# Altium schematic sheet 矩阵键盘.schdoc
size 297 x 210 mm; Symbol: Sheet-Symbol_A4; Company: 嘉立创EDA; Version: V1.0; Page Size: A4; @Project Name: 矩阵键盘; @Page Count: 1; @Update Date: 2024-04-23; @Create Date: 2024-04-23; @Schematic Name: Schematic1; @Page No: 1; @Page Name: P1; Device: Sheet-Symbol_A4
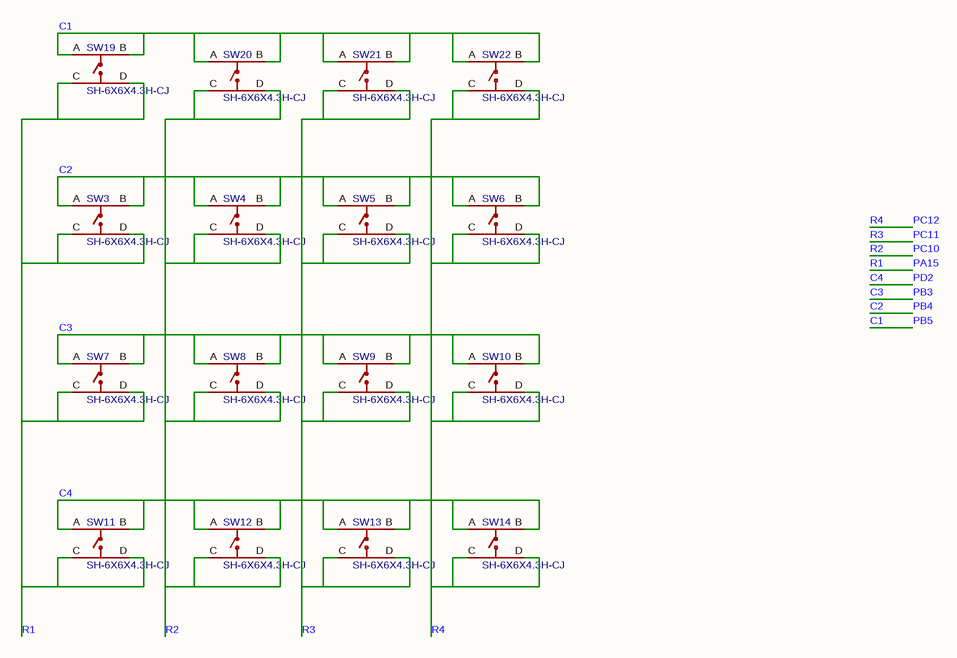
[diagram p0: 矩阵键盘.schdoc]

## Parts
SW3  SH-6X6X4.3H-CJ  [SW-TH_SH-6X6X4.3H-CJ]
SW4  SH-6X6X4.3H-CJ  [SW-TH_SH-6X6X4.3H-CJ]
SW5  SH-6X6X4.3H-CJ  [SW-TH_SH-6X6X4.3H-CJ]
SW6  SH-6X6X4.3H-CJ  [SW-TH_SH-6X6X4.3H-CJ]
SW7  SH-6X6X4.3H-CJ  [SW-TH_SH-6X6X4.3H-CJ]
SW8  SH-6X6X4.3H-CJ  [SW-TH_SH-6X6X4.3H-CJ]
SW9  SH-6X6X4.3H-CJ  [SW-TH_SH-6X6X4.3H-CJ]
SW10  SH-6X6X4.3H-CJ  [SW-TH_SH-6X6X4.3H-CJ]
SW11  SH-6X6X4.3H-CJ  [SW-TH_SH-6X6X4.3H-CJ]
SW12  SH-6X6X4.3H-CJ  [SW-TH_SH-6X6X4.3H-CJ]
SW13  SH-6X6X4.3H-CJ  [SW-TH_SH-6X6X4.3H-CJ]
SW14  SH-6X6X4.3H-CJ  [SW-TH_SH-6X6X4.3H-CJ]
SW19  SH-6X6X4.3H-CJ  [SW-TH_SH-6X6X4.3H-CJ]
SW20  SH-6X6X4.3H-CJ  [SW-TH_SH-6X6X4.3H-CJ]
SW21  SH-6X6X4.3H-CJ  [SW-TH_SH-6X6X4.3H-CJ]
SW22  SH-6X6X4.3H-CJ  [SW-TH_SH-6X6X4.3H-CJ]

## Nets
C1: SW19.A SW19.B SW20.A SW20.B SW21.A SW21.B SW22.A SW22.B  [also labelled PB5]
C2: SW3.A SW3.B SW4.A SW4.B SW5.A SW5.B SW6.A SW6.B  [also labelled PB4]
C3: SW7.A SW7.B SW8.A SW8.B SW9.A SW9.B SW10.A SW10.B  [also labelled PB3]
C4: SW11.A SW11.B SW12.A SW12.B SW13.A SW13.B SW14.A SW14.B  [also labelled PD2]
PA15: SW3.C SW3.D SW7.C SW7.D SW11.C SW11.D SW19.C SW19.D  [also labelled R1]
PC10: SW4.C SW4.D SW8.C SW8.D SW12.C SW12.D SW20.C SW20.D  [also labelled R2]
PC11: SW5.C SW5.D SW9.C SW9.D SW13.C SW13.D SW21.C SW21.D  [also labelled R3]
PC12: SW6.C SW6.D SW10.C SW10.D SW14.C SW14.D SW22.C SW22.D  [also labelled R4]

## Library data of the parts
SW3-SW14 SW19-SW22 = SH-6X6X4.3H-CJ: 电路结构:单刀单掷;按钮形状:圆形按钮;作用力:2.5N;安装方式:直插;开关长度:6mm;开关宽度:6mm;开关高度:4.3mm;带支架:不带支架;触点电流:50mA;额定电压:12V;带灯:无;工作寿命:10万次;; Manufacturer: SHOU HAN(首韩); 3D Model: 7465a1c6ddb3456bb37faad11a123e5a0819f05c4eef4c71ace90d822a990e87; 3D Model Transform: 236.22,307.086,0,90,0,0,0,0,-137.795; Circuit: 单刀单掷; Actuator Style: 圆形按钮; Operating Force: 2.5N; Switch Height: 4.3mm; with Bracket: 不带支架; Contact Current: 50mA; Voltage Rating: 12V; Actuator/Cap Color: 黑色; With Lamp: 无; Life: 10万次; AddInBom: yes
